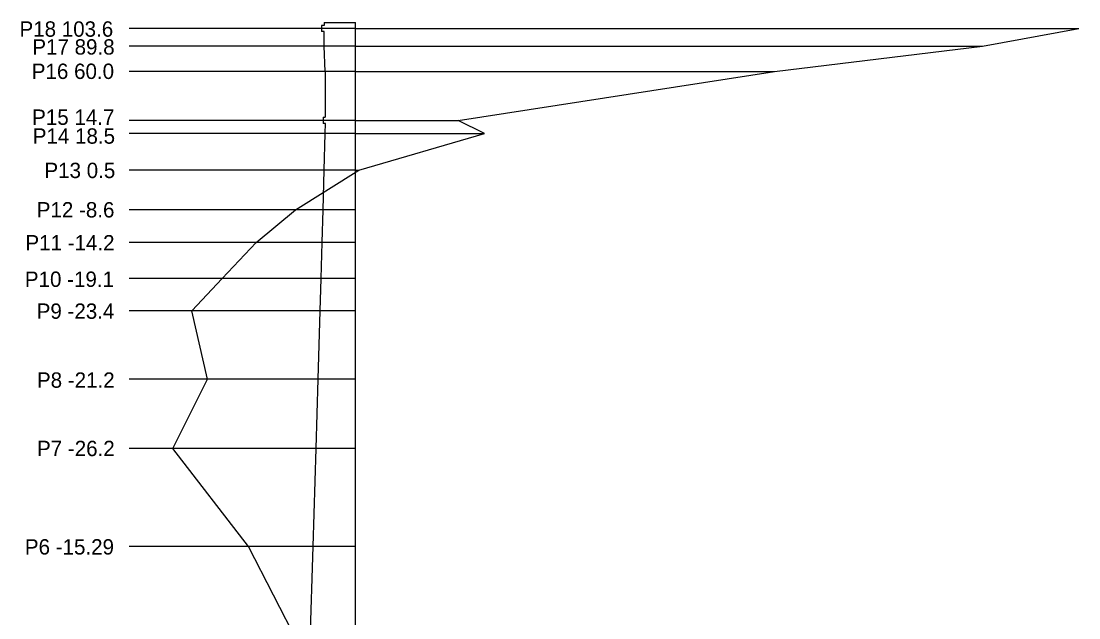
# Model space of a CAD drawing. Extents: x 138 to 264, y -75 to 121.
# Drawn here: x 230.9 to 246.04, y 99.53 to 108.07 of the extents above; entities that cross this region are included whole.
import ezdxf

# ---------------------------------------------------------------- set-up
doc = ezdxf.new("R2010")
doc.units = 0
doc.layers.add('Standart wykresów', color=7, linetype='Continuous')
doc.layers.add('Wykresy 4 maj 2008', color=7, linetype='Continuous')

msp = doc.modelspace()

# ---------------------------------------------------------------- linework, layer by layer
at = {"layer": 'Standart wykresów'}
for p, q in [((235.685, 107.967), (232.448, 107.967)), ((235.202, 108.009), (235.202, 107.967)), ((235.24, 108.009), (235.202, 108.009)), ((235.202, 107.967), (235.202, 107.925)), ((235.24, 108.051), (235.24, 108.009)), ((235.24, 108.051), (235.685, 108.051)), ((235.685, 87.967), (235.685, 108.051)), ((235.24, 107.925), (235.202, 107.925)), ((235.24, 107.711), (235.24, 107.925)), ((235.685, 107.711), (232.448, 107.711)), ((235.255, 107.348), (235.24, 107.711)), ((235.685, 107.348), (232.448, 107.348)), ((235.255, 107.348), (235.255, 106.694)), ((235.685, 106.65), (232.448, 106.65)), ((235.225, 106.694), (235.225, 106.65)), ((235.225, 106.694), (235.255, 106.694)), ((235.225, 106.65), (235.225, 106.606)), ((235.259, 106.606), (235.225, 106.606)), ((235.255, 106.463), (235.259, 106.606)), ((235.685, 106.463), (232.448, 106.463)), ((235.24, 105.937), (235.255, 106.463)), ((235.685, 105.937), (232.448, 105.937)), ((235.225, 105.369), (235.24, 105.937)), ((235.685, 105.937), (235.733, 105.937)), ((234.83, 105.369), (232.448, 105.369)), ((235.21, 104.901), (235.225, 105.369)), ((234.265, 104.901), (232.448, 104.901)), ((235.197, 104.384), (235.21, 104.901)), ((233.777, 104.384), (232.448, 104.384)), ((235.18, 103.925), (235.197, 104.384)), ((233.344, 103.925), (232.448, 103.925)), ((235.153, 102.945), (235.18, 103.925)), ((233.567, 102.945), (232.448, 102.945)), ((235.123, 101.951), (235.153, 102.945)), ((233.07, 101.951), (232.448, 101.951)), ((235.083, 100.549), (235.123, 101.951)), ((234.156, 100.549), (232.448, 100.549)), ((235.038, 99.158), (235.083, 100.549))]:
    msp.add_line(p, q, dxfattribs=at)
at = {"layer": 'Wykresy 4 maj 2008'}
for p, q in [((235.685, 107.967), (246.042, 107.967)), ((235.685, 107.711), (244.665, 107.711)), ((235.685, 107.348), (241.683, 107.348)), ((235.685, 106.65), (237.155, 106.65)), ((235.685, 106.463), (237.534, 106.463)), ((235.685, 105.369), (234.83, 105.369)), ((235.685, 104.901), (234.265, 104.901)), ((235.685, 104.384), (233.777, 104.384)), ((235.685, 103.925), (233.344, 103.925)), ((235.685, 102.945), (233.567, 102.945)), ((235.685, 101.951), (233.07, 101.951)), ((235.685, 100.549), (234.156, 100.549))]:
    msp.add_line(p, q, dxfattribs=at)
msp.add_lwpolyline([(235.685, 92.253), (235.666, 93.698), (235.639, 95.074), (235.677, 96.441), (235.319, 97.799), (234.872, 99.158), (234.156, 100.549), (233.07, 101.951), (233.567, 102.945), (233.344, 103.925), (233.777, 104.384), (234.265, 104.901), (234.83, 105.369), (235.733, 105.937), (237.534, 106.463), (237.155, 106.65), (241.683, 107.348), (244.665, 107.711), (246.042, 107.967)], dxfattribs=at)

# ---------------------------------------------------------------- texts
for s, p in [('P18 103.6', (230.877, 107.848)), ('P17 89.8', (231.061, 107.592)), ('P16 60.0', (231.053, 107.243)), ('P15 14.7', (231.058, 106.586)), ('P14 18.5', (231.067, 106.316)), ('P13 0.5', (231.234, 105.824)), ('P12 -8.6', (231.124, 105.26)), ('P11 -14.2', (230.962, 104.788)), ('P10 -19.1', (230.954, 104.266)), ('P9 -23.4', (231.123, 103.809)), ('P8 -21.2', (231.127, 102.822)), ('P7 -26.2', (231.128, 101.843)), ('P6 -15.29', (230.954, 100.434))]:
    msp.add_text(s, height=0.22, dxfattribs=at).set_placement(p)

doc.saveas('drawing.dxf')
